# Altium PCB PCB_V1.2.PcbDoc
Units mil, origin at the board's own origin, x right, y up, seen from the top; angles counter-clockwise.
Board outline 1605 x 645 mil, 2 copper layers (Top Layer, Bottom Layer); 19 components, 19 nets, 81 pads, 27 vias.
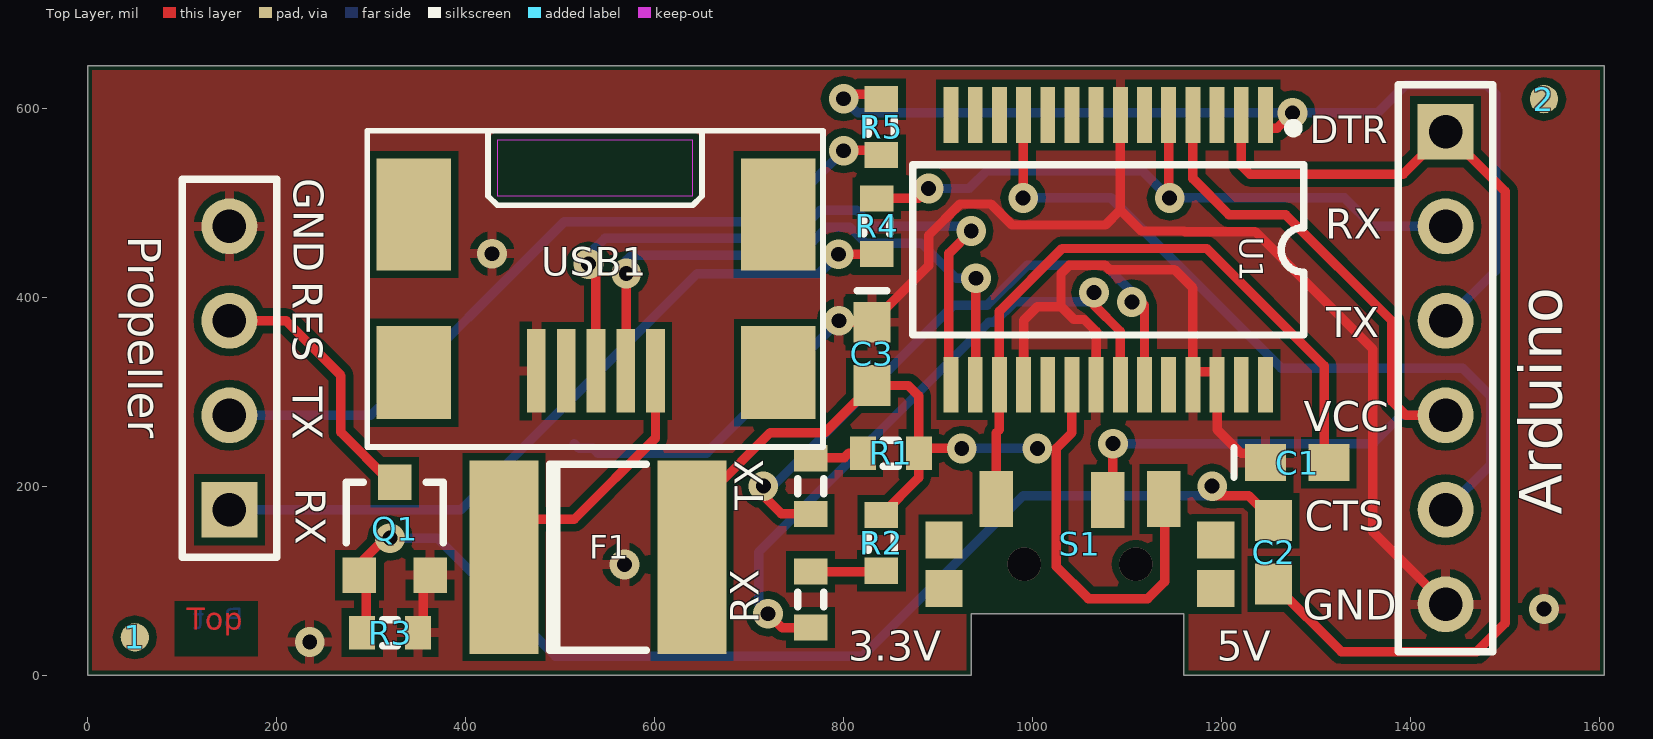
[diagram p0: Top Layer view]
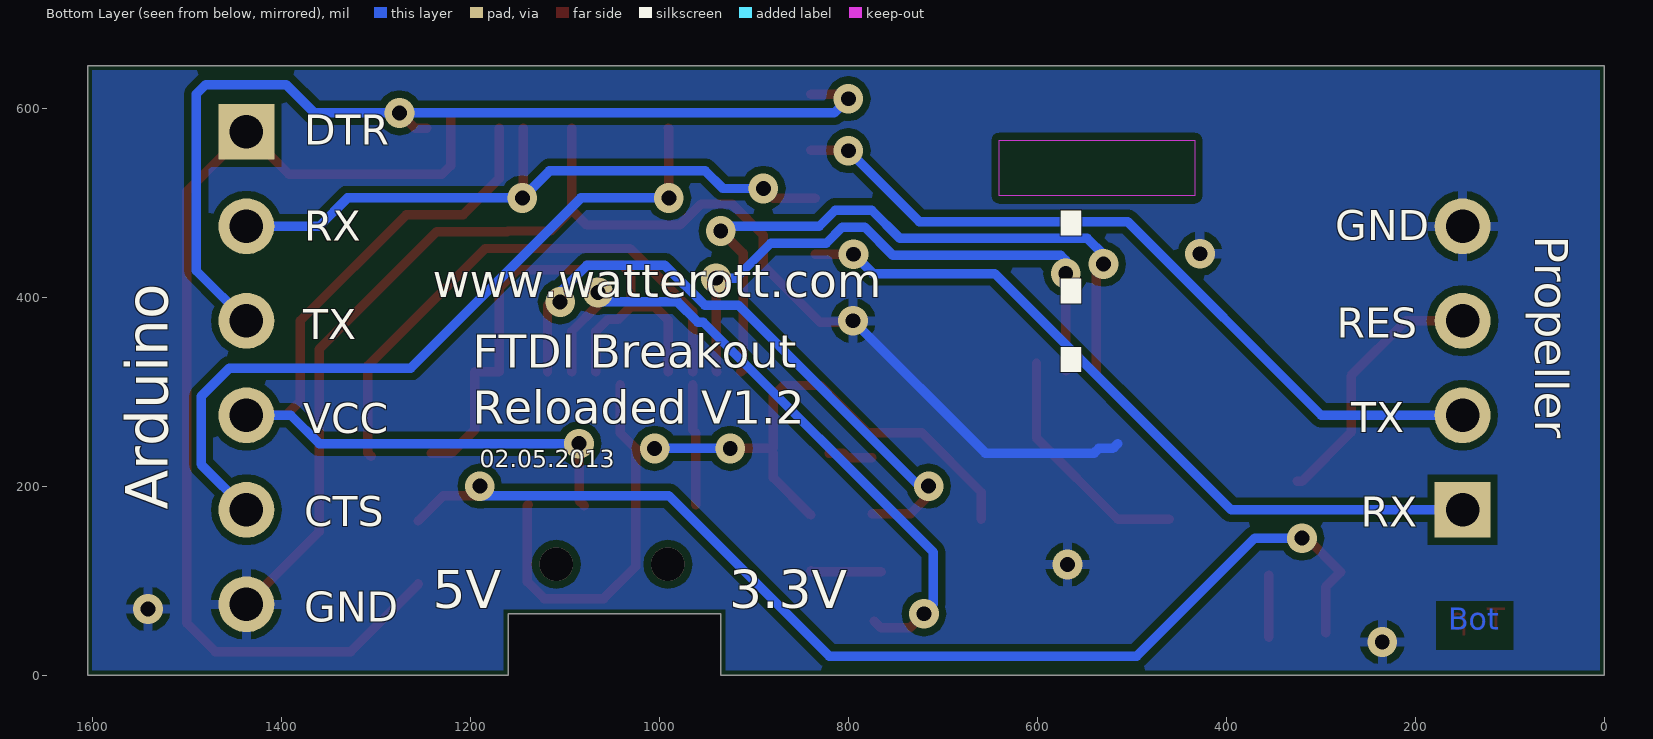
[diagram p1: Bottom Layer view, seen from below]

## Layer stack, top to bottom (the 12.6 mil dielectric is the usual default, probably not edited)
Top Layer: signal copper 1.4
Dielectric: dielectric 12.6, FR-4, Dk 4.8
Bottom Layer: signal copper 1.4

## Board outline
0,0 935,0 935,65 1160,65 1160,0 1605,0 1605,645 0,645

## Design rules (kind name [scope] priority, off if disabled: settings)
Clearance Clearance_2 [InNet('GND') vs OnLayer('Mechanical 1')] p1: gap=19.68
Clearance [All] p2: gap=7.87
FabricationTestPointUsage TestPointUsage [All] p1: valid=0 allowmultiple=FALSE
FabricationTestpoint Testpoint [All] p1: side=3 testpointundercomponent=TRUE minsize=40 maxsize=100 preferedsize=60 minholesize=0 maxholesize=40 preferedholesize=32 testpointgrid=1 allowsidetop=TRUE allowsidebottom=TRUE usegrid=TRUE gridtolerance=0.01
PlaneClearance PlaneClearance_1 [InNet('GND') And OnLayer('Mechanical 1')] p1: clearance=20
PlaneClearance [All] p2: clearance=19.68
PolygonConnect [All] p1: connectstyle=Relief reliefconductorwidth=10 reliefentries=4 polygonreliefangle="90 Angle"
RoutingVias [All] p1: holewidth=15.75 width=31.5 viastyle="Through Hole" minholewidth=11.81 minwidth=27.56 maxholewidth=23.62 maxwidth=39.37
SilkscreenOverComponentPads [All] p1: minsilkscreentomaskgap=10
SolderMaskExpansion [All] p1: expansion=4
Width [All] p1: maxlimit=10 minlimit=10 preferedwidth=10
24 further rules are at their usual default settings.

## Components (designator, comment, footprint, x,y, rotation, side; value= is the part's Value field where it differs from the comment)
1 "1" Paser_0,762mm 50,40 r270 top
2 "1" Paser_0,762mm 1541.1,609.57 r270 top
Arduino "Header 6H" HDR1X6 1437,575 r270 top
C1 "C0603" 0603 1280,225 r0 top
C2 "10nF" 0603 1255,130 r270 top
C3 "2,2µ" 0603 830,340 r270 top
F1 "Fuse 1" 2220 540,125 r0 top
Propeller "Header 4" HDR1X4 150,175 r90 top
Q1 "QNPN" SOT-23B 325,155 r0 top
R1 "Res3" RESC1608L 850,235 r0 top
R2 "Res3" RESC1608L 840,140 r90 top
R3 "33k" RESC1608L 320,45 r180 top
R4 "150" RESC1608L 835,475 r270 top
R5 "150" RESC1608L 840,580 r270 top
RX "LED2" RESC1608L 765,80 r270 top
S1 "SW-SPDT" "SMD Switch" 1050.03,117.36 r0 top
TX "LED2" RESC1608L 765,200 r270 top
U1 "FT232RL" PCBComponent_1 1080,450 r180 top
USB1 "USB_Con" "Molex 548190572" 345,487.44 r270 top

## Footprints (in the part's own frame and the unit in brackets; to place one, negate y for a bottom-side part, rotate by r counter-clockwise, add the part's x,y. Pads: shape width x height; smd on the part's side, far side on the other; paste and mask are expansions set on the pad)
0603 [mm] "Chip Capacitor; Body 1.6 x 0.8 mm (LxW typ)"
  rect 1.1x1 smd: 1(-0.85,0) 2(0.85,0)
  silkscreen extent -1.7,-0.4 -1.7,0.4
2220 [mm] "Chip Capacitor; Body 5.7 x 5.0 mm (LxW typ)"
  rect 1.85x5.2 smd: 1(-2.525,0) 2(2.525,0)
  silkscreen extent -1.3,-2.5 1.3,2.5
HDR1X4 [mm] "Connector; Header; 4 Position"
  rect 1.5x1.5 hole 0.9: 1(0,0)
  round 1.5 hole 0.9: 2(2.54,0) 3(5.08,0) 4(7.62,0)
  silkscreen extent -1.27,-1.27 8.89,1.27
HDR1X6 [mm] "Connector; Header; 6 Position"
  rect 1.5x1.5 hole 0.9: 1(0,0)
  round 1.5 hole 0.9: 2(2.54,0) 3(5.08,0) 4(7.62,0) 5(10.16,0) 6(12.7,0)
  silkscreen extent -1.27,-1.27 13.97,1.27
"Molex 548190572" [mm] "mini Usb 5  pol"
  rect 2.25x0.5 smd: 1(4.2,6.5) 2(4.2,5.7) 3(4.2,4.9) 4(4.2,3.3) 5(4.2,4.1)
  rect 3x2 smd: B1(0,0) B3(0,9.8)
  rect 2.5x2 smd: B2(4.25,0) B4(4.25,9.8)
  Keep-Out Layer region: -2,2.25 -0.5,2.25 -0.5,7.5 -2,7.5
  silkscreen extent -2.25,-1.25 6.25,11
Paser_0,762mm [mil]
  round 30 smd: 1(0,0)
PCBComponent_1 [mm]
  rect 0.4x1.5 smd: 1(-4.225,-3.625) 2(-3.575,-3.625) 3(-2.925,-3.625) 4(-2.275,-3.625) 5(-1.625,-3.625) 6(-0.975,-3.625) 7(-0.325,-3.625) 8(0.325,-3.625) 9(0.975,-3.625) 10(1.625,-3.625) 11(2.275,-3.625) 12(2.925,-3.625) 13(3.575,-3.625) 14(4.225,-3.625) 15(4.225,3.625) 16(3.575,3.625) 17(2.925,3.625) 18(2.275,3.625) 19(1.625,3.625) 20(0.975,3.625) 21(0.325,3.625) 22(-0.325,3.625) 23(-0.975,3.625) 24(-1.625,3.625) 25(-2.275,3.625) 26(-2.925,3.625) 27(-3.575,3.625) 28(-4.225,3.625)
  silkscreen extent -5.25,-3.4 5.25,2.29
RESC1608L [mm] "Chip Resistor, Body 1.6x0.8mm, IPC High Density"
  rect 0.7x0.9 smd: 1(-0.75,0) 2(0.75,0)
  silkscreen extent -0.2,-0.35 0.2,0.35, body extent -0.85,-0.48 0.85,0.48, height 0.6
"SMD Switch" [mm] "4ucon 19192"
  rect 0.9x1.5 smd: 1(-2.25,1.75) 2(0.75,1.725) 3(2.25,1.75)
  rect 1x1 smd: M0(-3.65,-0.65) M1(-3.65,0.65) M2(3.65,-0.65) M3(3.65,0.65)
SOT-23B [mm] "SOT-23; 3 Leads; Body 3.0 x 2.6 mm, inc. leads (LxW max)"
  rect 0.9x0.95 smd: 1(-0.95,-1.25) 2(0.95,-1.25) 3(0,1.25)
  silkscreen extent -1.3,-0.38 1.3,1.25

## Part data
Arduino: "Header, 6-Pin, Right Angle"
C1: "Ceramic Chip Capacitor - Standard"
C2 C3: library part C0603, "Ceramic Chip Capacitor - Standard"
F1: "Fuse"
Propeller: "Header, 4-Pin"
Q1: "NPN Bipolar Transistor"
R1 R2: "Resistor"
R3 R4 R5: library part Res3, "Resistor"
RX TX: "Typical RED, GREEN, YELLOW, AMBER GaAs LED"
S1: "SPDT Subminiature Toggle Switch, Right Angle Mounting, Vertical Actuation"
U1: library part FT232RQ

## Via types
v1: diameter 31.5, hole 15.75, Top Layer to Bottom Layer, tented both sides, 21 vias
v2: diameter 31.5, hole 15.75, Top Layer to Bottom Layer, 4 vias
v3: diameter 35.43, hole 35.43, Top Layer to Bottom Layer, 2 vias

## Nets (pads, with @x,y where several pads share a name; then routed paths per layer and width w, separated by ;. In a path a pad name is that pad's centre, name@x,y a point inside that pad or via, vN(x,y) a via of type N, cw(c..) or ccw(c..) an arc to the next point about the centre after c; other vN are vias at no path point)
3.3V: C1.2 S1.1 U1.17 | length 712.1
  Top Layer w10: S1.1@961.45,180.47 961.45,256.45 964.84,259.84 U1.17 ; U1.17@964.84,321.06 964.84,385.12 1031.22,451.5 1184.31,451.5 1308.46,327.34 1308.46,235 C1.2@1305,231.54
5V: C3.2 F1.2 R1.2 R2.2 S1.3 U1.20 | length 980.3
  Top Layer w10: F1.2@659.41,165 659.41,193.64 722.42,256.65 780.12,256.65 C3.2 868.46,306.54 879.53,295.47 879.53,240 v2(925,240) ; R2.2 879.53,209.06 R1.2 ; U1.20 1041.61,256.61 1025,240 1025,115 1059.02,80.98 1121.76,80.98 1139.68,98.9 1139.68,179.41 S1.3@1138.61,180.47
  Bottom Layer w10: v2(925,240) v2(1005,240)
GND: Arduino.6 C1.1 C3.1 Propeller.4 Q1.2 R3.1 U1.7 U1.18 U1.21 U1.25 U1.26 USB1.4 | length 2123.5
  Top Layer w10: R3.1@355,40 Q1.2@355,105.79 ; v1(795,375) 793.46,373.46 C3.1 890,433.46 890,465.48 923.14,498.62 955.9,498.62 978.14,476.38 1076.97,476.38 1092.8,492.2 ; U1.18@990.43,321.06 990.43,375.43 1005,390 1030,390 ; U1.21@1067.2,321.06 1067.2,363.88 1054.7,376.38 1043.62,376.38 1030,390 ; U1.7@1092.8,578.94 1092.8,492.2 ; C1.1@1241.54,235 1220,235 1195.16,259.84 1195.16,321.06 1169.57,321.06 1169.57,409.57 1150,429.13 1081.34,429.13 1076.86,433.62 1038.62,433.62 1030,425 1030,390 ; Arduino.6 1360,152 1360,345 1235.63,469.37 1161.19,469.37 1160.56,470 1115,470 1092.8,492.2
  Bottom Layer w10: 515,245 520,240 535,240 540,235 655,235 v1(795,375)
  other v1: 235,35 1541,70 568,117 428,446
NetArduino_1: Arduino.1 C2.2 U1.2 | length 1125.3
  Top Layer w10: U1.2 1220.75,539.25 1230,530 1392,530 Arduino.1 1500,512 1500,55 1470,25 1326.54,25 C2.2
NetArduino_2: Arduino.2 R4.1 U1.5 | length 712.7
  Top Layer w10: R4.1 879.53,504.53 v1(890,515) ; U1.5@1143.98,578.94 1143.98,506.02 v1(1145,505)
  Bottom Layer w10: v1(890,515) 932.76,515 951.38,533.62 1116.38,533.62 v1(1145,505) 1330,505 1360,475 Arduino.2
NetArduino_3: Arduino.3 R5.1 U1.1 | length 1051.9
  Top Layer w10: v1(800,610) 804.53,614.53 R5.1@840,614.53 ; U1.1@1246.34,578.94 1258.94,578.94 v1(1275,595)
  Bottom Layer w10: v1(800,610) 815,595 v1(1275,595) 1365,595 1395,625 1480,625 1490,615 1490,428 Arduino.3
NetArduino_4: Arduino.4 S1.2 U1.4 | length 906.7
  Top Layer w10: S1.2@1079.56,179.49 1085,184.93 v2(1085,245) ; U1.4@1169.57,578.94 1169.57,525.43 1207.76,487.24 1267.76,487.24 1380,375 1380,290 1395,275 Arduino.4
  Bottom Layer w10: v2(1085,245) 1360,245 1390,275 Arduino.4
NetArduino_5: Arduino.5 U1.11 | length 796
  Top Layer w10: v1(990,505) 990,578.5 U1.11@990.43,578.94
  Bottom Layer w10: v1(990,505) 1083,505 1263,325 1455,325 1485,295 1485,223 Arduino.5
NetC2_1: C2.1 Q1.1 R3.2 | length 1214.6
  Top Layer w10: R3.2@295,45 295,93.19 279.09,109.09 315,145 v1(320,145) ; v2(1190,200) 1190,190 1228.46,190 C2.1
  Bottom Layer w10: v1(320,145) 370,145 495,20 820,20 990,190 1190,190 v2(1190,200)
NetF1_1: F1.1 USB1.1 | length 255
  Top Layer w10: F1.1@460.59,165 515,165 600.91,250.91 USB1.1@600.91,330
NetPropeller_1: Propeller.1 R4.2 | length 797
  Top Layer w10: v1(794.53,445.47) R4.2
  Bottom Layer w10: Propeller.1 395,175 645,425 774.06,425 v1(794.53,445.47)
NetPropeller_2: Propeller.2 R5.2 | length 806.2
  Top Layer w10: v1(800,555) 800.47,555.47 R5.2@840,555.47
  Bottom Layer w10: Propeller.2 299.52,275 504.52,480 725,480 v1(800,555)
NetPropeller_3: Propeller.3 Q1.3 | length 280.6
  Top Layer w10: Propeller.3 210,375 268,317 268,257 320,205 Q1.3@325,205
NetR1_1: R1.1 TX.1 | length 47.5
  Top Layer w10: TX.1@775,230 800.47,230 805.47,235 R1.1
NetR2_1: R2.1 RX.1 | length 75.4
  Top Layer w10: RX.1 839.05,109.53 R2.1
NetRX_2: RX.2 U1.22 | length 698.4
  Top Layer w10: v1(720,65) 735,50 765.4,50 RX.2@772.7,57.3 ; v1(1065,405) 1065,391.67 1092.8,363.88 U1.22@1092.8,321.06
  Bottom Layer w10: v1(720,65) 710,75 710,130 953.5,373.5 959.26,373.5 980.76,395 1060,395 1065,400 v1(1065,405)
NetTX_2: TX.2 U1.23 | length 680.4
  Top Layer w10: v1(715,200) 715,190 734.06,170.94 TX.2@775,170.94 ; v1(1105,395) 1105,393.23 1106.61,391.61 1118.39,391.61 U1.23@1118.39,321.06
  Bottom Layer w10: v1(715,200) 725,200 916.38,391.38 951.86,391.38 994.1,433.62 1076.86,433.62 1103.15,407.33 1103.15,391.38 1105,393.23 v1(1105,395)
NetU1_15: U1.15 USB1.3 | length 722.4
  Top Layer w10: v1(530,435) 537.91,427.09 USB1.3 ; USB1.3@537.91,320 USB1.3@540,322.09 ; U1.15@913.66,321.06 911.38,323.35 911.38,446.38 v1(935,470)
  Bottom Layer w10: v1(530,435) 530,445 547.13,462.13 745.43,462.13 775.27,491.97 813.79,491.97 830.76,475 930,475 v1(935,470)
NetU1_16: U1.16 USB1.2 | length 623.4
  Top Layer w10: USB1.2 570,322.68 v1(570,425) ; U1.16@939.25,321.06 940,321.81 v1(940,420)
  Bottom Layer w10: v1(570,425) 570,439.02 575.24,444.25 752.83,444.25 782.67,474.09 806.38,474.09 823.35,457.13 882.12,457.13 919.24,420 v1(940,420)
pads on no net: 1.1 2.1 S1.M0 S1.M1 S1.M2 S1.M3 U1.3 U1.6 U1.8 U1.9 U1.10 U1.12 U1.13 U1.14 U1.19 U1.24 U1.27 U1.28 USB1.5 USB1.B1 USB1.B2 USB1.B3 USB1.B4
copper on no net:
  other v3: 990.98,117.36 1109.09,117.36

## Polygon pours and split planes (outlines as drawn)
GND on Bottom Layer "GND" (solid, remove dead copper, pour order 4): 5,5 930,5 930,70 1165,70 1165,5 1600,5 1600,640 5,640
GND on Top Layer "GND" (solid, remove dead copper, pour order 3): 5,5 930,5 930,70 1165,70 1165,5 1600,5 1600,640 5,640

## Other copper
Top Layer:
  text "Top" at 105,40 h39.37
Bottom Layer:
  text "Bot" at 165,40 h39.37

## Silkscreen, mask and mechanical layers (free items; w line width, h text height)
Top Overlay:
  text "DTR" at 1293,563 h28.94
  text "GND" at 218,526 h31.5 r270
  text "RX" at 1309.66,461.97 h31.5
  text "RES" at 217,417 h31.5 r270
  text "TX" at 1310.65,357.64 h31.5
  text "TX" at 217,305 h31.5 r270
  text "VCC" at 1286.65,258.23 h31.5
  text "RX" at 220,198 h31.5 r270
  text "CTS" at 1288,153 h31.5
  text "GND" at 1285.66,58.43 h31.5
  text "3.3V" at 805,15 h31.5
  text "5V" at 1195,15 h31.5
Bottom Overlay:
  text "DTR" at 1375.66,561.35 h31.5
  text "Propeller" at 73,465 h35 r90
  text "GND" at 285,460 h31.5
  text "RX" at 1375.66,459.97 h31.5
  text "www.watterott.com" at 1240,400 h35
  text "RES" at 283,357 h31.5
  text "TX" at 1376.65,355.64 h31.5
  text "FTDI Breakout" at 1197.32,325.16 h35
  text "⋮" at 670,280 h314.96
  text "Reloaded V1.2" at 1197.32,266.1 h35
  text "TX" at 268,257 h31.5
  text "VCC" at 1376.65,256.23 h31.5
  text "02.05.2013" at 1190,220 h18
  text "Arduino" at 1520,175 h44.88 r270
  text "CTS" at 1375.66,157.8 h31.5
  text "RX" at 258,157 h31.5
  text "3.3V" at 926,71 h40
  text "5V" at 1240,71 h40
  text "GND" at 1375.66,56.43 h31.5
Mechanical 2:
  lines w0.04: 0,0 0,645 240,645 1605,645 1605,0 1160,0 1160,65 935,65 935,0 235,0 0,0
